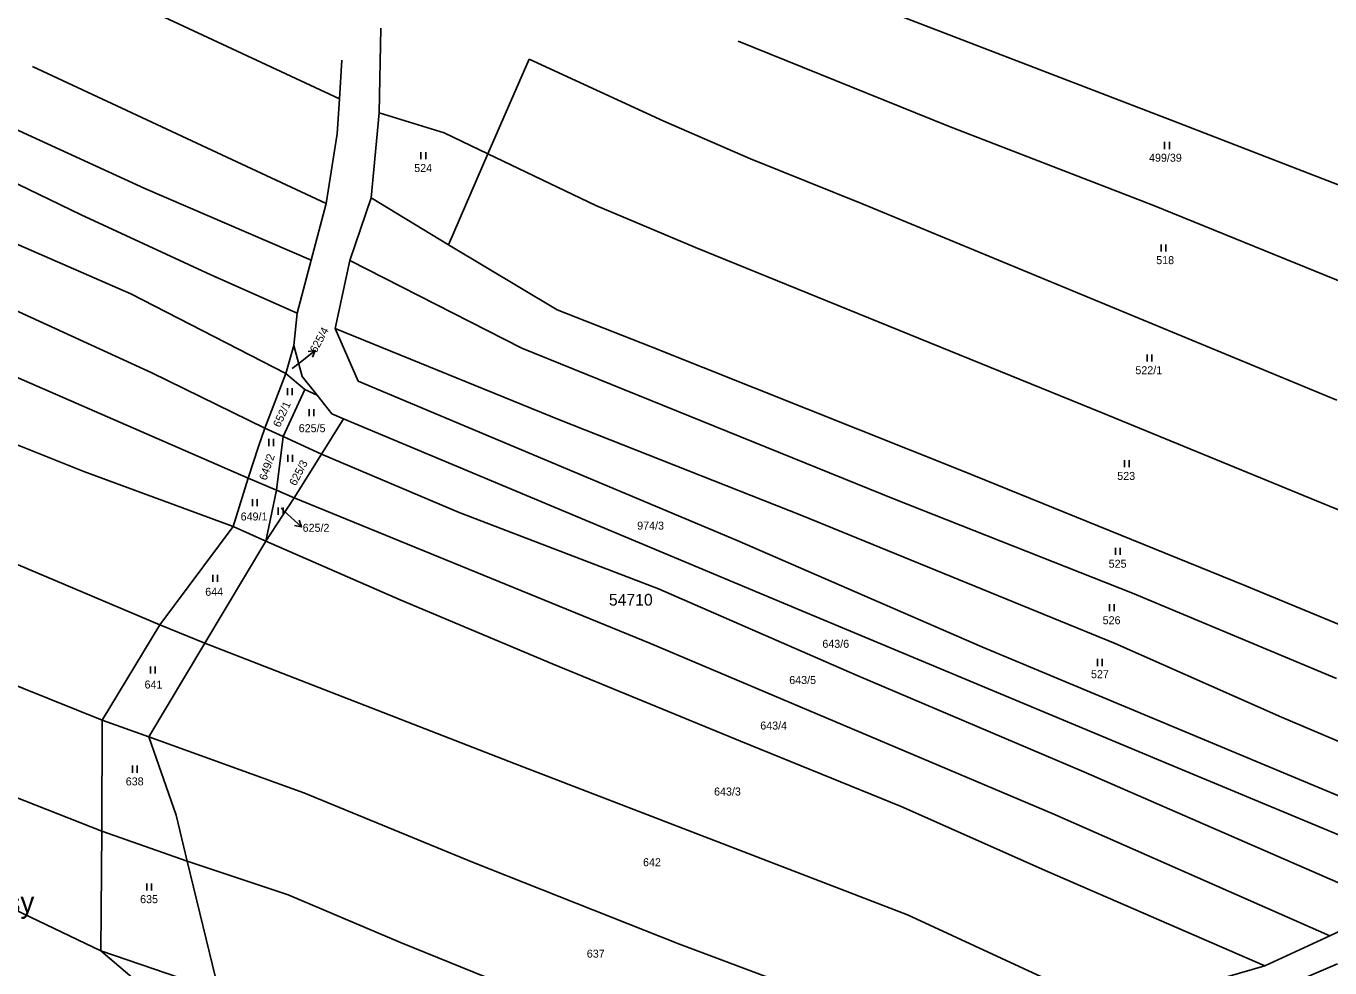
# Model space of a CAD drawing. Extents: x -749173 to -746119, y -1132678 to -1130338.
# Drawn here: x -748707.5 to -748430.5, y -1130902.1 to -1130701.9 of the extents above; entities that cross this region are included whole.
import ezdxf

# ---------------------------------------------------------------- set-up
doc = ezdxf.new("R2010")
doc.units = 0
for name, color, linetype in [('Vrstva 1', 7, 'Continuous'), ('Vrstva 15', 7, 'Continuous'), ('Vrstva 16', 7, 'Continuous'), ('Vrstva 18', 7, 'Continuous'), ('Vrstva 25', 7, 'Continuous'), ('Vrstva 53', 7, 'Continuous'), ('Vrstva 6', 7, 'Continuous')]:
    doc.layers.add(name, color=color, linetype=linetype)

msp = doc.modelspace()

# ---------------------------------------------------------------- linework, layer by layer
at = {"layer": 'Vrstva 1'}
for points in [[(-748632.44, -1130720.29), (-748632.1, -1130702.29)], [(-748640.37, -1130709.13), (-748640.91, -1130717.3)], [(-748640.91, -1130717.3), (-748641.41, -1130724.78)], [(-748634.19, -1130738.36), (-748632.44, -1130720.29)], [(-748641.41, -1130724.78), (-748643.72, -1130739.57)], [(-748638.72, -1130751.72), (-748634.19, -1130738.36)], [(-748643.72, -1130739.57), (-748646.89, -1130751.6)], [(-748646.89, -1130751.6), (-748649.86, -1130762.87)], [(-748641.83, -1130766.14), (-748638.72, -1130751.72)], [(-748649.86, -1130762.87), (-748650.55, -1130769.73)], [(-748636.94, -1130777.36), (-748641.83, -1130766.14)], [(-748650.55, -1130769.73), (-748652.25, -1130775.75)], [(-748650.55, -1130769.73), (-748648.82, -1130776.37)], [(-748652.25, -1130775.75), (-748656.74, -1130787.3)], [(-748648.82, -1130776.37), (-748645.64, -1130780.35)], [(-748556.44, -1130811.2), (-748636.94, -1130777.36)], [(-748645.64, -1130780.35), (-748642.52, -1130784.27)], [(-748644.72, -1130792.86), (-748640.02, -1130785.32)], [(-748642.52, -1130784.27), (-748640.02, -1130785.32)], [(-748640.02, -1130785.32), (-748543.51, -1130825.81)], [(-748656.74, -1130787.3), (-748658.12, -1130791.2)], [(-748658.12, -1130791.2), (-748660.26, -1130797.97)], [(-748650.5, -1130802.12), (-748644.72, -1130792.86)], [(-748660.26, -1130797.97), (-748663.47, -1130808.22)], [(-748656.51, -1130811.34), (-748650.5, -1130802.12)], [(-748663.47, -1130808.22), (-748679.08, -1130829.15)], [(-748669.5, -1130833.07), (-748656.51, -1130811.34)], [(-748504.41, -1130833.78), (-748556.44, -1130811.2)], [(-748543.51, -1130825.81), (-748464.71, -1130858.77)], [(-748679.08, -1130829.15), (-748691.29, -1130849.38)], [(-748681.37, -1130852.94), (-748669.5, -1130833.07)], [(-748407.29, -1130874.39), (-748504.41, -1130833.78)], [(-748691.29, -1130849.38), (-748691.38, -1130873.01)], [(-748675.59, -1130869.57), (-748681.37, -1130852.94)], [(-748464.71, -1130858.77), (-748407.23, -1130882.69)], [(-748673.21, -1130879.38), (-748675.59, -1130869.57)], [(-748691.38, -1130873.01), (-748691.56, -1130898.44)], [(-748666.52, -1130906.98), (-748673.21, -1130879.38)], [(-748430.56, -1130895.23), (-748417.27, -1130888.93)], [(-748444.32, -1130901.6), (-748430.56, -1130895.23)], [(-748691.56, -1130898.44), (-748682.52, -1130906.16)], [(-748476.62, -1130910.98), (-748444.32, -1130901.6)], [(-748443.77, -1130907.57), (-748428.88, -1130901.17)]]:
    msp.add_lwpolyline(points, dxfattribs=at)
at = {"layer": 'Vrstva 16'}
for p, q in [((-748647.52, -1130771.06), (-748646.03, -1130770.85)), ((-748649.42, -1130806.91), (-748648.98, -1130808.34))]:
    msp.add_line(p, q, dxfattribs=at)
for points in [[(-748649.19, -1130773.31), (-748646.03, -1130770.85), (-748646.6, -1130772.24)], [(-748650.91, -1130774.65), (-748649.19, -1130773.31)], [(-748653.26, -1130804.36), (-748651.91, -1130805.62)], [(-748651.91, -1130805.62), (-748648.98, -1130808.34), (-748650.44, -1130808.01)]]:
    msp.add_lwpolyline(points, dxfattribs=at)
at = {"layer": 'Vrstva 25'}
for p, q in [((-748465.61, -1130726.5), (-748465.61, -1130728)), ((-748464.61, -1130728), (-748464.61, -1130726.5)), ((-748623.58, -1130728.69), (-748623.58, -1130730.19)), ((-748622.58, -1130730.19), (-748622.58, -1130728.69)), ((-748466.33, -1130748.27), (-748466.33, -1130749.77)), ((-748465.33, -1130749.77), (-748465.33, -1130748.27)), ((-748469.33, -1130771.67), (-748469.33, -1130773.17)), ((-748468.33, -1130773.17), (-748468.33, -1130771.67)), ((-748651.92, -1130778.84), (-748651.92, -1130780.34)), ((-748650.92, -1130780.34), (-748650.92, -1130778.84)), ((-748647.31, -1130783.32), (-748647.31, -1130784.82)), ((-748646.31, -1130784.82), (-748646.31, -1130783.32)), ((-748655.92, -1130789.63), (-748655.92, -1130791.13)), ((-748654.92, -1130791.13), (-748654.92, -1130789.63)), ((-748651.89, -1130792.99), (-748651.89, -1130794.49)), ((-748650.89, -1130794.49), (-748650.89, -1130792.99)), ((-748474.17, -1130794.14), (-748474.17, -1130795.64)), ((-748473.17, -1130795.64), (-748473.17, -1130794.14)), ((-748659.37, -1130802.4), (-748659.37, -1130803.9)), ((-748658.37, -1130803.9), (-748658.37, -1130802.4)), ((-748653.88, -1130804.23), (-748653.88, -1130805.73)), ((-748652.88, -1130805.73), (-748652.88, -1130804.23)), ((-748476.04, -1130812.79), (-748476.04, -1130814.29)), ((-748475.04, -1130814.29), (-748475.04, -1130812.79)), ((-748667.82, -1130818.52), (-748667.82, -1130820.02)), ((-748666.82, -1130820.02), (-748666.82, -1130818.52)), ((-748477.36, -1130824.75), (-748477.36, -1130826.25)), ((-748476.36, -1130826.25), (-748476.36, -1130824.75)), ((-748681.02, -1130837.99), (-748681.02, -1130839.49)), ((-748680.02, -1130839.49), (-748680.02, -1130837.99)), ((-748479.91, -1130836.4), (-748479.91, -1130837.9)), ((-748478.91, -1130837.9), (-748478.91, -1130836.4)), ((-748684.85, -1130859.07), (-748684.85, -1130860.57)), ((-748683.85, -1130860.57), (-748683.85, -1130859.07)), ((-748681.79, -1130884.1), (-748681.79, -1130885.6)), ((-748680.79, -1130885.6), (-748680.79, -1130884.1))]:
    msp.add_line(p, q, dxfattribs=at)
at = {"layer": 'Vrstva 6'}
for points in [[(-748684.38, -1130697.1), (-748640.91, -1130717.3)], [(-748463.67, -1130722.09), (-748521.14, -1130699.97)], [(-748511.54, -1130723.13), (-748556.18, -1130705.09)], [(-748706.1, -1130710.47), (-748643.72, -1130739.57)], [(-748609.37, -1130729.04), (-748600.62, -1130708.93)], [(-748600.62, -1130708.93), (-748572.02, -1130722.05)], [(-748618.62, -1130724.53), (-748632.44, -1130720.29)], [(-748572.02, -1130722.05), (-748553.57, -1130730.11)], [(-748402.55, -1130745.71), (-748463.67, -1130722.09)], [(-748710.6, -1130723.33), (-748682.21, -1130736.37)], [(-748609.37, -1130729.04), (-748618.62, -1130724.53)], [(-748468.11, -1130739.92), (-748511.54, -1130723.13)], [(-748617.75, -1130748.36), (-748609.37, -1130729.04)], [(-748586.47, -1130739.97), (-748609.37, -1130729.04)], [(-748553.57, -1130730.11), (-748529.63, -1130739.69)], [(-748695.74, -1130742.02), (-748713.67, -1130733.35)], [(-748682.21, -1130736.37), (-748646.89, -1130751.6)], [(-748617.75, -1130748.36), (-748634.19, -1130738.36)], [(-748565.25, -1130748.92), (-748586.47, -1130739.97)], [(-748529.63, -1130739.69), (-748429.06, -1130781.38)], [(-748424.93, -1130757.48), (-748468.11, -1130739.92)], [(-748723.6, -1130742.09), (-748685.2, -1130758.76)], [(-748668.24, -1130754.72), (-748695.74, -1130742.02)], [(-748594.66, -1130762.19), (-748617.75, -1130748.36)], [(-748478.86, -1130784.11), (-748565.25, -1130748.92)], [(-748602.16, -1130770.3), (-748638.72, -1130751.72)], [(-748649.86, -1130762.87), (-748668.24, -1130754.72)], [(-748680.72, -1130775.54), (-748712.39, -1130761.05)], [(-748685.2, -1130758.76), (-748652.25, -1130775.75)], [(-748574.85, -1130769.98), (-748594.66, -1130762.19)], [(-748641.83, -1130766.14), (-748594.17, -1130785.58)], [(-748729.5, -1130767.78), (-748660.26, -1130797.97)], [(-748522.97, -1130802.41), (-748602.16, -1130770.3)], [(-748508.41, -1130796.48), (-748574.85, -1130769.98)], [(-748656.74, -1130787.3), (-748680.72, -1130775.54)], [(-748648.22, -1130779.11), (-748652.25, -1130775.75)], [(-748652.83, -1130789.11), (-748648.22, -1130779.11)], [(-748648.22, -1130779.11), (-748645.64, -1130780.35)], [(-748594.17, -1130785.58), (-748542.67, -1130805.9)], [(-748430.59, -1130803.91), (-748478.86, -1130784.11)], [(-748695.21, -1130796.54), (-748721.13, -1130786.22)], [(-748652.83, -1130789.11), (-748656.74, -1130787.3)], [(-748654.25, -1130800.53), (-748652.83, -1130789.11)], [(-748644.72, -1130792.86), (-748652.83, -1130789.11)], [(-748615.5, -1130805.28), (-748644.72, -1130792.86)], [(-748663.47, -1130808.22), (-748695.21, -1130796.54)], [(-748448.56, -1130820.81), (-748508.41, -1130796.48)], [(-748660.26, -1130797.97), (-748654.25, -1130800.53)], [(-748656.51, -1130811.34), (-748654.25, -1130800.53)], [(-748654.25, -1130800.53), (-748650.5, -1130802.12)], [(-748650.5, -1130802.12), (-748574.8, -1130833.09)], [(-748472.42, -1130822.39), (-748522.97, -1130802.41)], [(-748573.14, -1130821.5), (-748615.5, -1130805.28)], [(-748354.99, -1130834.29), (-748430.59, -1130803.91)], [(-748656.51, -1130811.34), (-748663.47, -1130808.22)], [(-748542.67, -1130805.9), (-748476.15, -1130833.14)], [(-748725.39, -1130809.48), (-748679.08, -1130829.15)], [(-748628.03, -1130823.85), (-748656.51, -1130811.34)], [(-748530.93, -1130839.89), (-748573.14, -1130821.5)], [(-748391.34, -1130844.41), (-748448.56, -1130820.81)], [(-748691.29, -1130849.38), (-748752.74, -1130824.68)], [(-748595.49, -1130837.5), (-748628.03, -1130823.85)], [(-748429.14, -1130840.54), (-748472.42, -1130822.39)], [(-748679.08, -1130829.15), (-748669.5, -1130833.07)], [(-748669.5, -1130833.07), (-748603.55, -1130858.65)], [(-748574.8, -1130833.09), (-748489.17, -1130869.4)], [(-748476.15, -1130833.14), (-748440.81, -1130848.76)], [(-748555.74, -1130853.87), (-748595.49, -1130837.5)], [(-748482.75, -1130860.42), (-748530.93, -1130839.89)], [(-748681.37, -1130852.94), (-748691.29, -1130849.38)], [(-748440.81, -1130848.76), (-748384.89, -1130872.51)], [(-748648.46, -1130864.82), (-748681.37, -1130852.94)], [(-748521.6, -1130867.76), (-748555.74, -1130853.87)], [(-748733.87, -1130856.25), (-748691.38, -1130873.01)], [(-748603.55, -1130858.65), (-748520.26, -1130890.78)], [(-748417.27, -1130888.93), (-748482.75, -1130860.42)], [(-748612.61, -1130879.56), (-748648.46, -1130864.82)], [(-748490.53, -1130881.55), (-748521.6, -1130867.76)], [(-748489.17, -1130869.4), (-748430.56, -1130895.23)], [(-748691.38, -1130873.01), (-748673.21, -1130879.38)], [(-748651.82, -1130886.51), (-748673.21, -1130879.38)], [(-748568.68, -1130897.02), (-748612.61, -1130879.56)], [(-748691.56, -1130898.44), (-748724.77, -1130882.55)], [(-748444.32, -1130901.6), (-748490.53, -1130881.55)], [(-748627.96, -1130896.65), (-748651.82, -1130886.51)], [(-748520.26, -1130890.78), (-748476.62, -1130910.98)], [(-748604.69, -1130906.09), (-748627.96, -1130896.65)], [(-748691.56, -1130898.44), (-748666.52, -1130906.98)], [(-748539.81, -1130907.88), (-748568.68, -1130897.02)]]:
    msp.add_lwpolyline(points, dxfattribs=at)

# ---------------------------------------------------------------- texts
at = {"layer": 'Vrstva 15'}
msp.add_text('Pod lesy', height=4.4, dxfattribs=at).set_placement((-748728.28, -1130890.33))
at = {"layer": 'Vrstva 16'}
msp.add_text('625/4', height=1.7, rotation=61.3138, dxfattribs=at).set_placement((-748645.82, -1130771.47))
msp.add_text('625/2', height=1.7, dxfattribs=at).set_placement((-748648.71, -1130809.36))
at = {"layer": 'Vrstva 18'}
for s, height, p in [('499/39', 1.7, (-748468.93, -1130730.7)), ('524', 1.7, (-748625.01, -1130732.89)), ('518', 1.7, (-748467.41, -1130752.47)), ('625/4', 0.1, (-748650.91, -1130774.65)), ('522/1', 1.7, (-748471.83, -1130775.87)), ('625/5', 1.7, (-748649.54, -1130788.19)), ('523', 1.7, (-748475.68, -1130798.34)), ('649/1', 1.7, (-748661.88, -1130806.96)), ('974/3', 1.7, (-748577.65, -1130808.9)), ('525', 1.7, (-748477.5, -1130817)), ('644', 1.7, (-748669.4, -1130822.96)), ('526', 1.7, (-748478.78, -1130829.01)), ('643/6', 1.7, (-748538.32, -1130834.02)), ('641', 1.7, (-748682.29, -1130842.68)), ('643/5', 1.7, (-748545.35, -1130841.72)), ('527', 1.7, (-748481.25, -1130840.48)), ('643/4', 1.7, (-748551.51, -1130851.4)), ('638', 1.7, (-748686.28, -1130863.27)), ('643/3', 1.7, (-748561.32, -1130865.42)), ('642', 1.7, (-748576.41, -1130880.45)), ('635', 1.7, (-748683.23, -1130888.3)), ('637', 1.7, (-748588.35, -1130899.88))]:
    msp.add_text(s, height=height, dxfattribs=at).set_placement(p)
for s, height, rotation, p in [('652/1', 1.7, 65.1033, (-748653.56, -1130787.3)), ('649/2', 1.7, 71.3298, (-748656.41, -1130798.55)), ('625/3', 1.7, 62.5924, (-748650.17, -1130799.73)), ('625/2', 0.1, 65.6101, (-748653.26, -1130804.36))]:
    msp.add_text(s, height=height, rotation=rotation, dxfattribs=at).set_placement(p)
at = {"layer": 'Vrstva 53'}
msp.add_text('54710', height=2.5, dxfattribs=at).set_placement((-748583.66, -1130825.06))

doc.saveas('drawing.dxf')
